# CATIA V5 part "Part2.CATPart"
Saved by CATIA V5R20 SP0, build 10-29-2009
Part number: 梯
Bounding box of the stored display mesh (mm): x -98.739 to 98.739, y -98.544 to 98.544, z 0 to 41
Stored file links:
  D:\liandongzhou\Part2.CATPart
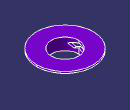
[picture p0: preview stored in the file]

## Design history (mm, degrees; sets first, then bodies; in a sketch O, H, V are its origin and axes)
Set1
  Sketch1 on xy-plane, origin (0, 0, 0), H (1, 0, 0), V (0, 1, 0)
    circle A1 centre (0, 0) radius 47.5
    circle A2 centre (0, 0) radius 55
    radius A2 = 55
    radius A1 = 47.5
Body1 (main body)
  Plane1: type Offset, RefPlane xy-plane, Offset 35
  Sketch2 on Plane1, origin (0, 0, 35), H (1, 0, 0), V (0, 1, 0)
    circle A1 centre (0, 0) radius 98.7386
    circle A2 centre (0, 0) radius 47.5
    radius A2 = 47.5
    radius A1 = 98.7386
  Pad1: profile Sketch2, direction (0, 0, 1), length 6
  Pad2: profile Sketch1, direction (0, 0, 1), length 35
  DatumSurface1
  Fillet1: radius 5, on edge [start face of Pad2 | face of Pad2 from Sketch1.A2]
  DatumSurface2
  Point1: type OnPlane, Support DatumSurface2, H 131.418, V -28.869, Direction (1, 0, 0)
  Sketch3 on yz-plane, origin (0, 0, 0), H (0, 1, 0), V (0, 0, 1)
    line L1 (-28.8024, 23.4484) -> (-14.6008, 11.8867)
    line L2 (-14.6008, 11.8867) -> (0, 18.1666)
    point P3 (0, 18.1666)
    line L3 (0, 18.1666) -> (18.8568, 11.8867)
    line L4 (18.8568, 11.8867) -> (37.1979, 23.4484)
    line L5 (37.1979, 23.4484) -> (5.15, 33.6308)
    line L6 (5.15, 33.6308) -> (-28.8024, 23.4484)
    coincidence: L1 O, P3 V, L4 O
  DatumSurface3
  Body2
    Pad3: profile Sketch3, direction (1, 0, 0), length 100, mirrored extent
  Remove1: tool Body2
  DatumSurface4
  Sketch4 on face of DatumSurface3, origin (0, 0, 124.801), H (1, 0, 0), V (0, 1, 0)
    circle A1 centre (0, 0) radius 98.7385
    radius A1 = 98.7385
  Pocket1: profile Sketch4, direction (0, 0, -1), length 35
  Sketch5 on face of DatumSurface4, origin (0, 0, 124.801), H (1, 0, 0), V (0, 1, 0)
    circle A1 centre (0, 0) radius 98.7385
    radius A1 = 98.7385
  Pocket2: profile Sketch5, direction (0, 0, -1), length 35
